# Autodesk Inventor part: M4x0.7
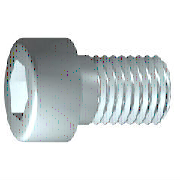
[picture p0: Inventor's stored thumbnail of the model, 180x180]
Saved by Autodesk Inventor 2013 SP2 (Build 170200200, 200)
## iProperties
IsCustomPart: 1
Created: 2009-02
Part Number: M4x0.7
Material: 강철, 연강
Description: 6각머리 태핑 나사
Document SubType Name: Modeling
Standard: KS B 1003
Designer: SeoGD™[esajin.kr]
Standards Organization: KS
Language: ko-KR
Size Designation: M 4 x 16
Categories: <MemberInstance><Categories><Category DisplayName="조임쇠" InternalName="e4da775c-781d-43d5-af7c-5136215cf5a6" Mnemonic="FSTN"><Category DisplayName="볼트" InternalN
Density: 7.86 g/cm^3
Mass: 2.62973 g
Surface Area: 3.81118 cm^2
Volume: 0.334572 cm^3
Author: SeoGD™[esajin.kr]
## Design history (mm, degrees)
sketch "스케치1"
  geometry: L1 (-1, 0)-(16, 0); L2 (16, 0)-(16, 2); L3 (16, 2)-(1.75, 2); L4 (1.75, 2)-(1.32, 2); L5 (1.32, 2)-(0, 2); L6 (0, 2)-(0, 3.5); L7 (0, 3.5)-(-4, 3.5); L8 (-4, 3.5)-(-4, 1.732); L9 (-4, 1.732)-(-2, 1.732); L10 (-2, 1.732)-(-1, 0); L11 (-8, 0)-(20, 0) reference; L12 (0, -0.7)-(0, 4.2) reference; L13 (1.75, 2)-(0, 2)
  constraints: 22 end point, 6 parallel, 2 collinear, 2 perpendicular, 1 horizontal, 1 point on line
  dimensions: "d1" = 14.25 distance from line of L3.end L2 (= GEL); "d2" = 0.42952 distance of L4.end L3.end (computed from GAL); "d3" = 4 distance between parallel lines of L8 L6 (= KOH); "d4" = 2 distance of L8.end L9.end (= INTI); "d5" = 60 deg angle of L10 L1; "d6" = 4 diameter of L3 L1 (= GD); "d7" = 4 diameter of L5 L1 (= BDM); "d8" = 3.4641 diameter of L9 L1 (= 1.1547 x SW); "d9" = 7 diameter of L7 L1 (= KOD); "d26" = 16 distance between parallel lines of L12 L2 (= NLG)
revolve "본체" sketch "스케치1" stored, may be unused: angle "d10" = 90 deg
sketch "스케치2"
  geometry: L1 (0, -4.9)-(0, 4.9) reference; L2 (-4.9, 0)-(4.9, 0) reference; L3 (1.732, 0)-(0.866, -1.5); L4 (0.866, -1.5)-(-0.866, -1.5); L5 (-0.866, -1.5)-(-1.732, 0); L6 (-1.732, 0)-(-0.866, 1.5); L7 (-0.866, 1.5)-(0.866, 1.5); L8 (0.866, 1.5)-(1.732, 0); 2 further points
  constraints: 12 end point, 1 coincident, 1 horizontal alignment, 1 point on line, 12 other
extrude "슬롯" join sketch "스케치2" stored distance "d11" = 10; taper "d12" = 0 deg
workplane "Work Plane1"
fillet "Fillet2" dims "d30" = 0.1 (= R)
body "Solid1"
fillet "모깎기1" dims "d17" = 0.4 (= RR)
feature "스레드" dims "d13" = 14.25 (= GEL), "d14" = 0
chamfer "모따기1" distance "d15" = 0.42941 (= -0.5 x SPD + 0.5 x GD); stored, may be unused: second distance "d16" = 0.42941 (= GUL), angle "d27" = 45 deg
other parameters: "GD" = 4 (= NND) [user parameter; used in 2 equation terms], "NLG" = 16 [user parameter; used in 1 equation term], "GEL" = 14.25 [user parameter; used in 2 equation terms], "KOD" = 7 [user parameter; used in 1 equation term], "KOH" = 4 [user parameter; used in 1 equation term], "INTI" = 2 [user parameter; used in 1 equation term], "GAL" = 0.42941 (= 0.61345 x PTC) [user parameter; used in 1 equation term], "GUL" = 0.42941 (= 0.61345 x PTC) [user parameter; used in 1 equation term], "BDM" = 4 (= NND) [user parameter; used in 1 equation term], "SW" = 3 [user parameter; used in 2 equation terms], "RR" = 0.4 [user parameter; used in 1 equation term], "SPD" = 3.14117 (= NND - 1.2269 x PTC) [user parameter; used in 1 equation term], "d19" = 0, "d28" = 0, "d29" = 0, "R" = 0.1 [user parameter; used in 1 equation term], "PHH" = 0.2 [user parameter], "GD1" = 3.14117 (= THREADDIA - 1.2269 x PTC) [user parameter], "THREADDIA" = 4 [user parameter; used in 1 equation term], "FAWI" = 45 deg [user parameter], "TPU" = 14.28571 (computed from PTC) [user parameter], "PTC" = 0.7 [user parameter; used in 5 equation terms], "NND" = 4 [user parameter; used in 3 equation terms], "TOA" = 30 deg [user parameter], "E0" = 3.465 (= 1.155 x SW) [user parameter]
